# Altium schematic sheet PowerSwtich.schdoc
size 266 x 137 mm
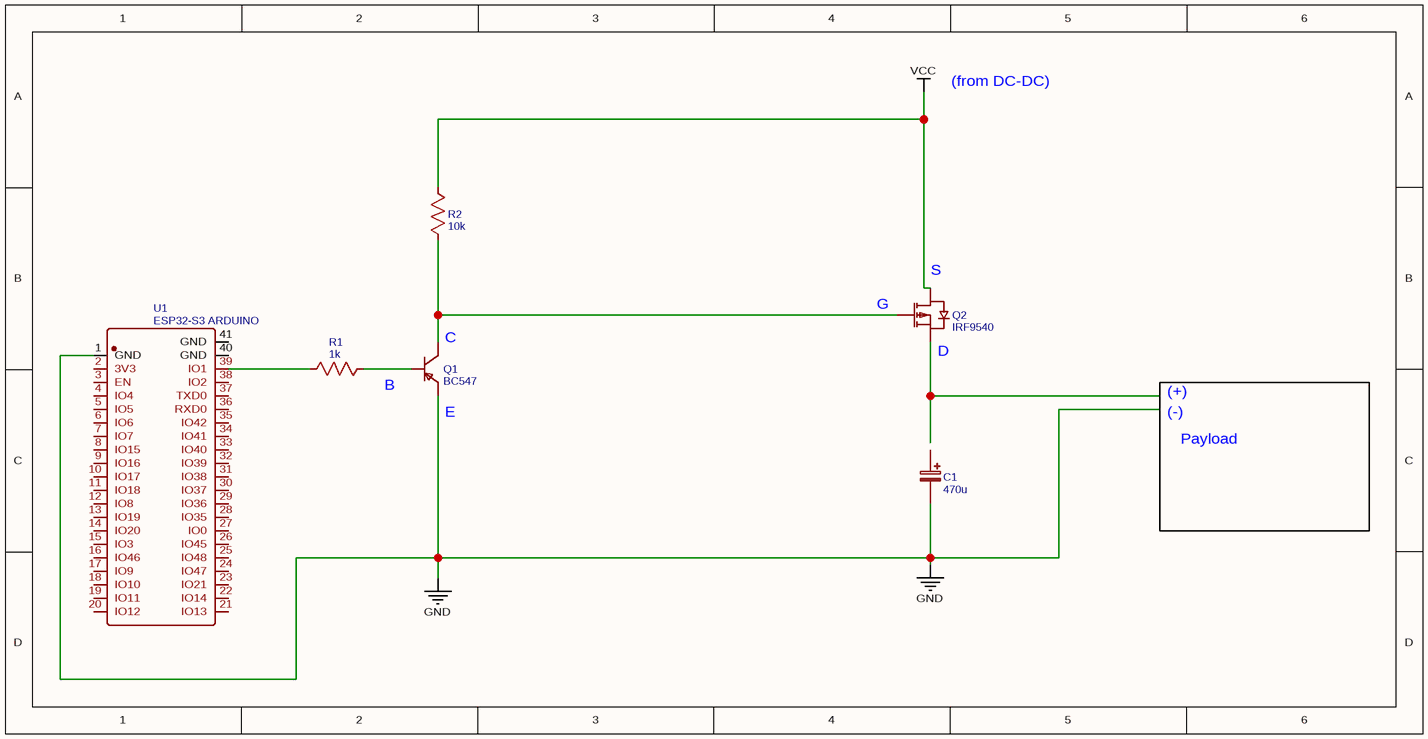
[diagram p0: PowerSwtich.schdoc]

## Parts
C1  470u  [CASE-A_3216]
Q1  BC547  [SOT-23-3_L2.9-W1.6-P1.90-LS2.8-TR-CW]
Q2  IRF9540  [TO-263-2_L10.0-W9.1-P5.08-LS15.2-BR]
R1  1k  [R0603]
R2  10k  [R0603]
U1  ESP32-S3 ARDUINO  [WIRELM-SMD_ESP32-S3-WROOM-1U]

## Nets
GND: C1.2 Q1.1(E) U1.1(GND)
VCC: Q2.4(D) R2.1
NetQ1_2: Q1.2(B) R1.2
NetQ1_3: Q1.3(C) Q2.1(G) R2.2
NetR1_1: R1.1 U1.39(IO1)

Not connected (* = marked no-connect by the designer): C1 1; Q2 3(S); U1 2(3V3) 3(EN) 4(IO4) 5(IO5) 6(IO6) 7(IO7) 8(IO15) 9(IO16) 10(IO17) 11(IO18) 12(IO8) 13(IO19) 14(IO20) 15(IO3) 16(IO46) 17(IO9) 18(IO10) 19(IO11) 20(IO12) 21(IO13) 22(IO14) 23(IO21) 24(IO47) 25(IO48) 26(IO45) 27(IO0) 28(IO35) 29(IO36) 30(IO37) 31(IO38) 32(IO39) 33(IO40) 34(IO41) 35(IO42) 36(RXD0) 37(TXD0) 38(IO2) 40(GND) 41(GND)

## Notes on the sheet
- (from DC-DC)
- (near Q2) S
- (near Q1) C
- (near Q2) G
- (near Q2) D
- B
- (near Q1) E
- (+)
- (-)
- Payload

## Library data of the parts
C1 = 470u: nameAlias: Value(F); Contributor: LCEDA_Lib
Q1 = BC547: Manufacturer: KEC; Manufacturer Part: 2N3906S-RTK/PS; Contributor: LCEDA_Lib
Q2 = IRF9540: Manufacturer: IR; Manufacturer Part: IRF5210STRLPBF; Paste Type: expand; Contributor: LCEDA_Lib
R1 = 1k: nameAlias: Value(Ω); Contributor: LCEDA_Lib
R2 = 10k: nameAlias: Value(Ω); Contributor: LCEDA_Lib
U1 = ESP32-S3 ARDUINO: Manufacturer: null; Manufacturer Part: ESP32-S3-WROOM-1U; Contributor: lcsc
